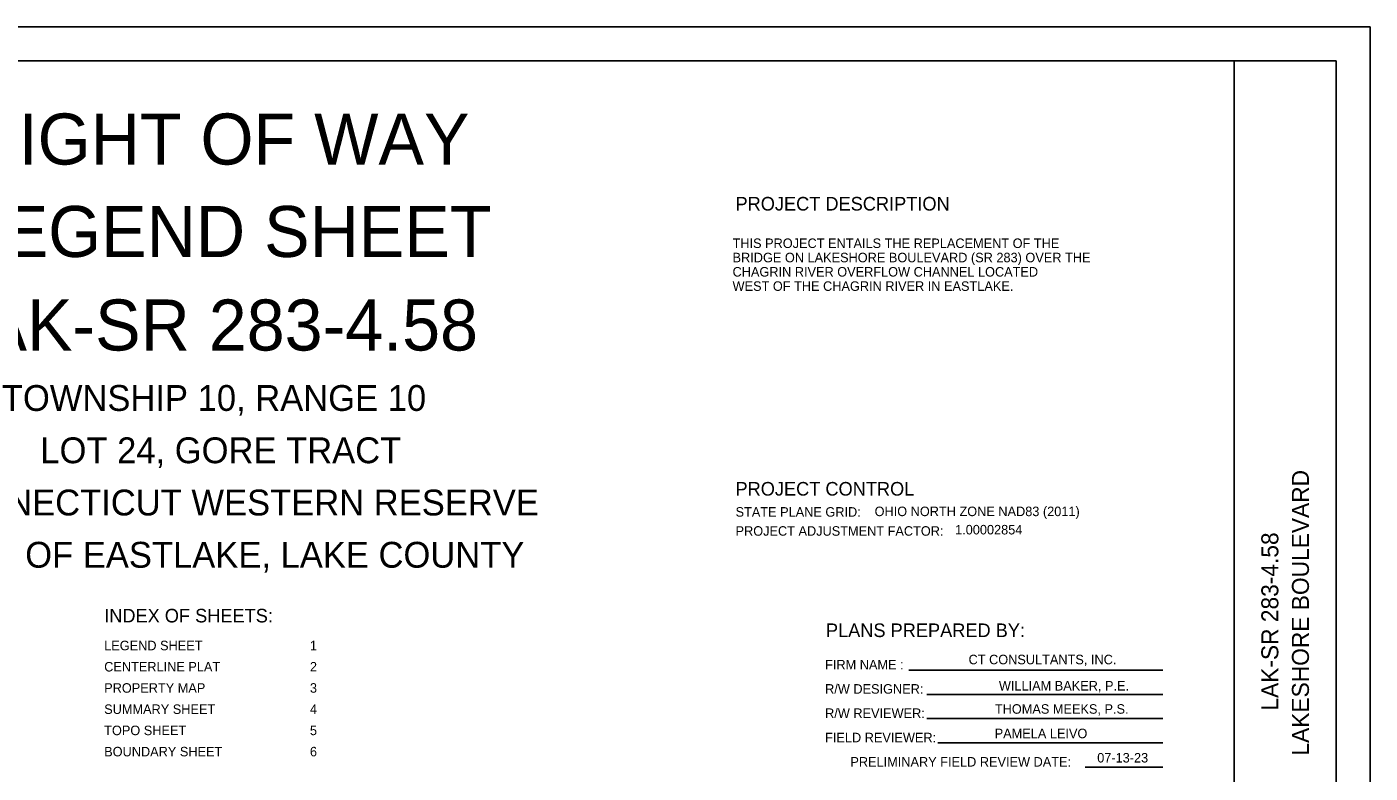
# Model space of a CAD drawing. Extents: x 0 to 34, y 0 to 22.
# Drawn here: x 14.24 to 34, y 11.03 to 22 of the extents above; entities that cross this region are included whole.
import ezdxf

# ---------------------------------------------------------------- set-up
doc = ezdxf.new("R2010")
doc.units = 0
for name, color, linetype in [('Default', 7, 'Continuous'), ('SH_Border', 7, 'Continuous'), ('SH_Cut_Line', 7, 'Continuous'), ('SH_Data', 7, 'Continuous'), ('SH_Text', 7, 'Continuous'), ('SN_P_Text', 7, 'Continuous')]:
    doc.layers.add(name, color=color, linetype=linetype)

msp = doc.modelspace()

# ---------------------------------------------------------------- linework, layer by layer
at = {"layer": 'Default'}
msp.add_line((1.5, 21.5), (32, 21.5), dxfattribs=at)
at = {"layer": 'SH_Border'}
msp.add_line((32, 0.5), (32, 21.5), dxfattribs=at)
msp.add_lwpolyline([(1.5, 21.5), (33.5, 21.5), (33.5, 0.5), (1.5, 0.5)], close=True, dxfattribs=at)
at = {"layer": 'SH_Cut_Line'}
msp.add_lwpolyline([(0, 0), (34, 0), (34, 22), (0, 22)], close=True, dxfattribs=at)
at = {"layer": 'SH_Text'}
for p, q in [((27.216, 12.544), (30.953, 12.544)), ((27.48, 12.187), (30.953, 12.187)), ((27.48, 11.83), (30.953, 11.83)), ((27.644, 11.473), (30.953, 11.473)), ((29.808, 11.115), (30.953, 11.115))]:
    msp.add_line(p, q, dxfattribs=at)

# ---------------------------------------------------------------- texts
at = {"layer": 'SH_Data'}
for s, height, p in [('RIGHT OF WAY', 0.75, (13.399, 19.976)), ('LEGEND SHEET', 0.75, (13.33, 18.617)), ('LAK-SR 283-4.58', 0.75, (13.018, 17.242)), ('TOWNSHIP 10, RANGE 10', 0.38, (13.876, 16.354)), ('LOT 24, GORE TRACT', 0.38, (14.442, 15.585)), ('CONNECTICUT WESTERN RESERVE', 0.38, (12.825, 14.817)), ('CITY OF EASTLAKE, LAKE COUNTY', 0.38, (12.921, 14.049)), ('INDEX OF SHEETS:', 0.2, (15.381, 13.244)), ('LEGEND SHEET', 0.14, (15.381, 12.835)), ('1', 0.14, (18.407, 12.835)), ('CENTERLINE PLAT', 0.14, (15.381, 12.523)), ('2', 0.14, (18.407, 12.523)), ('PROPERTY MAP', 0.14, (15.381, 12.211)), ('3', 0.14, (18.407, 12.211)), ('SUMMARY SHEET', 0.14, (15.381, 11.899)), ('4', 0.14, (18.407, 11.899)), ('TOPO SHEET', 0.14, (15.381, 11.587)), ('5', 0.14, (18.407, 11.587)), ('BOUNDARY SHEET', 0.14, (15.381, 11.275)), ('6', 0.14, (18.407, 11.275))]:
    msp.add_text(s, height=height, dxfattribs=at).set_placement(p)
for s, p in [('LAKESHORE BOULEVARD', (33.1, 11.287)), ('LAK-SR 283-4.58', (32.65, 11.948))]:
    msp.add_text(s, height=0.25, rotation=90, dxfattribs=at).set_placement(p)
at = {"layer": 'SH_Text'}
for s, height, p in [('THIS PROJECT ENTAILS THE REPLACEMENT OF THE', 0.14, (24.623, 18.749)), ('BRIDGE ON LAKESHORE BOULEVARD (SR 283) OVER THE', 0.14, (24.623, 18.539)), ('CHAGRIN RIVER OVERFLOW CHANNEL LOCATED ', 0.14, (24.623, 18.329)), ('WEST OF THE CHAGRIN RIVER IN EASTLAKE.', 0.14, (24.623, 18.119)), ('PROJECT CONTROL', 0.2, (24.666, 15.109)), ('STATE PLANE GRID:', 0.14, (24.667, 14.799)), (' OHIO NORTH ZONE NAD83 (2011)', 0.14, (26.66, 14.807)), ('PROJECT ADJUSTMENT FACTOR:', 0.14, (24.667, 14.519)), ('1.00002854', 0.14, (27.896, 14.538)), ('PLANS PREPARED BY:', 0.2, (25.996, 13.029)), ('FIRM NAME :', 0.14, (25.984, 12.554)), ('R/W DESIGNER:', 0.14, (25.984, 12.197)), ('R/W REVIEWER:', 0.14, (25.984, 11.84)), ('FIELD REVIEWER:', 0.14, (25.984, 11.482)), ('PRELIMINARY FIELD REVIEW DATE:', 0.14, (26.356, 11.125))]:
    msp.add_text(s, height=height, dxfattribs=at).set_placement(p)
at = {"layer": 'SN_P_Text'}
for s, height, p in [('PROJECT DESCRIPTION', 0.2, (24.666, 19.3)), ('CT CONSULTANTS, INC.', 0.14, (28.094, 12.629)), ('WILLIAM BAKER, P.E.', 0.14, (28.54, 12.243)), ('THOMAS MEEKS, P.S.', 0.14, (28.481, 11.902)), ('PAMELA LEIVO', 0.14, (28.478, 11.542)), ('07-13-23', 0.14, (29.986, 11.185))]:
    msp.add_text(s, height=height, dxfattribs=at).set_placement(p)

doc.saveas('drawing.dxf')
